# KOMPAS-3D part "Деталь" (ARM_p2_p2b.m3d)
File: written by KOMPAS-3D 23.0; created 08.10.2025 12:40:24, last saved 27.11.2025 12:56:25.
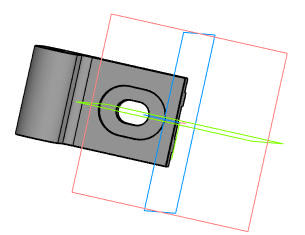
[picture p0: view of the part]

Document properties: Автор: ADMIN; Полное имя файла: D:\YandexDisk\Model\NVG\ARM mkII\ARM p2 p2b.m3d

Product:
- Part/product: Деталь
    Масса: 0.072746

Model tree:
1. Эскиз:1
2. Элемент выдавливания:1
     Расстояние 1 = 41
3. Эскиз:3  (with: Элемент выдавливания:1)
4. Элемент выдавливания:3
5. Эскиз:7  (with: Элемент выдавливания:1, Элемент выдавливания:3)
6. Элемент выдавливания:7
7. Эскиз:8  (with: Элемент выдавливания:1, Элемент выдавливания:7)
8. Элемент выдавливания:8
9. Эскиз:9  (with: Элемент выдавливания:1, Элемент выдавливания:7)
10. Элемент выдавливания:9
     Расстояние 2 = 1
11. Скругление:5  (with: Элемент выдавливания:8)
     Радиус = 3.15
12. Скругление:2  (with: Элемент выдавливания:7, Элемент выдавливания:3)
     Радиус = 6
13. Скругление:4  (with: Элемент выдавливания:7)
     Радиус = 2.5
14. Скругление:6  (with: Элемент выдавливания:9)
     Радиус = 6.8
15. Фаска:1  (with: Скругление:6, Элемент выдавливания:1, Скругление:5, Элемент выдавливания:3)
     Угол = 45; Длина 1 = 0.2; Длина 2 = 0.2

Expressions: v239/2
